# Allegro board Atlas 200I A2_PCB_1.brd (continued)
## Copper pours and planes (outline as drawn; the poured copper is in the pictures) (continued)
V_DV33_HUB on ART04: 93.03,95.62 96.99,95.62 98.65,97.28 98.65,104.14 97.84,104.95 97.84,105.18 97.54,105.49 96.49,105.49 94.64,103.63 94.64,101.85 93.27,100.48 93.27,99.95 93.45,99.77 96.75,99.77 97.26,99.26 97.26,98.32 96.34,97.41 91.29,97.41 90.27,96.39 90.27,94.49 90.6,94.16 91.57,94.16
V_DVDD_1V0_PHY0 on TOP (solid shape): 11.25,68.53 11.25,64.57 9.21,62.52 9.2,62.52 9.12,62.44 9.12,61.72 8.93,61.53 8.93,60.79 8.85,60.72 7.28,60.72 7.28,60.72 7.28,61.38 7.28,61.84 7.49,62.05 7.85,62.05 7.98,62.18 7.98,62.41 8.64,62.41 8.64,62.71 8.28,62.71 8.28,62.41 7.98,62.41 7.98,63.68 8.38,63.68 8.38,64.11 8.13,64.11 8.13,63.68 7.98,63.68 7.98,64.24 7.85,64.36 7.85,64.42 7.84,64.47 7.82,64.53 7.8,64.58 7.76,64.62 7.72,64.66 7.67,64.7 7.62,64.72 7.62,64.9 8.66,64.9 8.66,65.28 8.38,65.28 8.38,64.9 7.62,64.9 7.62,65.51 7.72,65.61 9.22,65.61 9.25,65.63 9.35,65.63 9.38,65.6 9.43,65.58 9.47,65.55 9.52,65.54 9.58,65.53 9.63,65.53 9.68,65.54 9.73,65.55 9.77,65.58 9.82,65.6 9.85,65.63 9.93,65.63 10.21,65.91 10.21,67.21 9.8,67.61 8.79,67.61 8.69,67.72 8.7,67.72 8.7,67.82 9.47,67.82 9.47,68.25 8.94,68.25 8.94,67.82 8.7,67.82 8.7,68.39 9.02,68.71 11.07,68.71
V_DVDD_1V0_PHY0 on BOTTOM (solid shape): outline of 125 points within 9.3,55.5 18.11,68.94
V_DVDD_1V0_PHY1 on TOP (solid shape): 50.36,28.66 50.71,28.66 51,28.38 51,27.7 50.79,27.5 49.94,27.5 49.92,27.51 49.88,27.54 49.83,27.56 49.79,27.57 49.74,27.58 49.71,27.58 49.63,27.66 49.63,27.83 50.68,27.83 50.68,28.11 49.97,28.11 49.97,27.83 49.63,27.83 49.63,28.26 50.1,28.73 50.36,28.73
V_DVDD_1V0_PHY1 on TOP (solid shape): 57.23,42.47 57.23,42.06 56.58,41.42 56.58,40.63 56.55,40.6 54.93,40.6 54.93,41.26 54.93,41.43 55.4,41.89 55.4,41.91 55.98,41.91 55.98,42.21 56.74,42.21 56.74,42.47 56.34,42.47 56.34,42.21 55.98,42.21 55.98,42.34 55.7,42.34 55.7,41.91 55.4,41.91 55.4,41.93 55.4,41.93 55.4,42.45 55.55,42.6 57.1,42.6
V_STBY_1V8 on TOP (solid shape): 128.09,36.55 128.32,36.55 128.57,36.3 128.57,33.93 128.44,33.8 127.04,33.8 126.95,33.89 126.95,34.14 128.32,34.14 128.32,34.48 128.06,34.48 128.06,34.14 126.95,34.14 126.95,34.17 127.34,34.17 127.34,34.48 127.09,34.48 127.09,34.17 126.95,34.17 126.95,34.54 126.99,34.59 127.03,34.59 127.09,34.61 127.14,34.63 127.18,34.65 127.23,34.69 127.26,34.73 127.3,34.77 127.32,34.82 127.34,34.87 127.35,34.92 127.36,34.95 127.37,34.97 127.64,35.23 127.64,36.58 127.69,36.63 128.02,36.63
V_STBY_1V8 on TOP (solid shape): 95.18,39.65 95.2,39.65 95.23,39.64 95.25,39.62 95.27,39.6 95.28,39.57 95.29,39.54 95.27,39.45 95.27,38.09 95.26,38.06 95.24,38.01 95.23,37.95 95.22,37.87 91.99,37.87 91.46,37.34 90.75,37.34 90.73,37.31 90.72,37.3 90.7,37.29 90.7,37.09 90.7,37.08 90.7,36.5 90.18,35.99 89.4,35.99 89.4,36.24 90.09,36.24 90.09,36.5 89.4,36.5 89.4,36.83 89.27,36.96 89,36.96 88.93,37.02 88.93,37.74 91.24,37.74 91.24,38.15 90.98,38.15 90.98,37.74 88.93,37.74 88.93,37.78 89.02,37.87 89.7,37.87 89.7,38.12 89.91,38.33 89.91,39.04 90.52,39.65
V_STBY_1V8 on TOP (solid shape): outline of 90 points within 109.58,47.73 126.77,71.37
V_STBY_1V8 on BOTTOM (solid shape): outline of 14136 points within 0.91,6.22 129.29,119.49
V_STBY_1V8 on ART04 (solid shape): outline of 300 points within 71.27,86.21 101.37,114.5
V_STBY_1V8 on TOP: 80.37,82.6 83.87,82.6 83.92,82.55 83.92,82.17 83.87,82.12 83.72,82.12 83.52,81.92 83.52,81.36 83.26,81.1 81.81,81.1 81.31,80.59 81.31,79.45 80.77,78.92 80.34,78.92 80.04,78.61 80.04,76.89 80.23,76.69 84.02,76.69 84.58,76.12 84.58,75.67 84.48,75.56 79.71,75.56 79.17,75.03 71.55,75.03 70.94,75.64 70.94,76.02 71.09,76.17 71.6,76.17 71.83,76.4 71.83,88.24 72.52,88.93 73.63,88.93 73.79,88.77 73.79,86.16 73.43,85.8 73.43,81.43 73.61,81.25 74.42,81.25 74.75,80.92 74.75,80.29 74.57,80.11 73.61,80.11 73.43,79.93 73.43,76.02 73.84,75.62 77.9,75.62 78.82,76.53 78.82,78.44 79.22,78.84 79.22,82.19 79.62,82.59 ; 5 cut-outs
V_STBY_3V3 on TOP (solid shape): 128.68,40.51 128.68,38.48 128.27,38.08 128.2,38.07 128.14,38.05 127.66,38.05 127.62,38.09 127.62,39.46 127.2,39.88 126.49,39.88 126.39,39.98 126.39,40.71 126.47,40.79 128.39,40.79
V_STBY_3V3 on TOP (solid shape): 3.59,48.18 3.59,47.48 3.33,47.22 1.47,47.22 1.35,47.09 0.86,47.09 0.64,47.32 0.64,47.71 3.3,47.71 3.3,48.05 2.92,48.05 2.92,47.71 0.64,47.71 0.64,48.16 0.84,48.36 3.41,48.36
V_STBY_3V3 on TOP (solid shape): 57.6,44.7 57.64,44.7 57.99,44.35 57.99,43.96 58.15,43.79 58.15,42.48 58.08,42.41 57.49,42.41 57.4,42.49 57.4,42.7 57.99,42.7 57.99,43.18 57.66,43.18 57.66,42.7 57.4,42.7 57.4,43.41 57.25,43.56 57.25,43.61 57.2,43.61 57.07,43.74 56.03,43.74 55.88,43.89 55.88,44.8 56.08,45 57.3,45
V_STBY_3V3 on TOP (solid shape): 84.41,110.92 89.43,110.92 89.56,110.79 89.56,109.96 89.43,109.83 83.45,109.83 83.26,110.02 83.26,110.15 88.23,110.15 88.23,110.57 87.92,110.57 87.92,110.15 83.26,110.15 83.26,110.59 83.9,110.59 83.9,111 83.49,111 83.49,110.59 83.26,110.59 83.26,111.22 83.36,111.32 84.01,111.32
V_STBY_3V3 on TOP (solid shape): 25.17,85.65 25.17,84.38 25.25,84.3 26.06,84.3 26.16,84.2 26.16,83.19 26.14,83.17 26.14,83.07 25.96,82.88 24.05,82.88 23.75,83.19 23.75,83.44 23.32,83.87 22.27,83.87 21.89,83.49 21.4,83.49 21.31,83.57 21.31,83.9 21.8,83.9 21.8,84.84 24.82,84.84 24.82,85.12 24.38,85.12 24.38,84.84 21.8,84.84 21.8,85.46 21.55,85.46 21.55,83.9 21.31,83.9 21.31,85.88 21.41,85.98 24.84,85.98
V_STBY_3V3 on TOP (solid shape): 114.17,27.66 114.17,26.42 114.2,26.39 114.2,26.34 114.25,26.34 114.33,26.26 116.04,26.26 116.12,26.18 116.12,25.21 115.86,24.94 112.9,24.94 112.75,25.1 112.75,25.25 115.87,25.25 115.87,25.53 114.3,25.53 114.3,25.25 112.75,25.25 112.75,25.76 115.87,25.76 115.87,26.04 114.3,26.04 114.3,25.76 112.75,25.76 112.75,26.44 113.23,26.92 113.23,27.38 113.43,27.58 113.67,27.58 113.69,27.61 113.71,27.61 113.71,27.63 113.79,27.71 114.12,27.71
V_STBY_3V3 on TOP (solid shape): 98.86,20.12 98.86,19.68 99.16,19.38 99.16,15.47 98.98,15.29 98.3,15.29 98.04,15.04 98.04,12.98 97.71,12.65 96.82,12.65 96.62,12.85 96.62,13.47 97.39,13.47 97.39,13.46 97.79,13.46 97.79,13.77 96.62,13.77 96.62,16.09 97.39,16.09 97.39,16.08 97.79,16.08 97.79,16.39 96.62,16.39 96.62,17.27 98.7,17.27 98.7,17.63 98.25,17.63 98.25,17.27 96.62,17.27 96.62,18.54 98.7,18.54 98.7,18.87 98.25,18.87 98.25,18.54 96.62,18.54 96.62,18.71 97.39,18.71 97.39,18.72 97.76,18.72 97.76,19 96.62,19 96.62,19.68 97.89,19.68 98.17,19.96 98.17,20.27 98.25,20.35 98.63,20.35
V_STBY_3V3 on TOP (solid shape): 47.47,118.33 47.47,117.91 47.61,117.91 47.61,117.73 47.67,117.73 47.7,117.7 47.7,116.92 47.55,116.76 47.02,116.76 46.99,116.74 46.94,116.74 46.94,116.69 46.14,115.89 45.22,115.89 44.55,115.21 44.55,114.86 44.53,114.84 44.53,113.94 44.55,113.92 44.55,113.36 44.42,113.36 44.42,112.65 43.1,112.65 42.98,112.78 42.98,112.83 44.15,112.83 44.15,113.23 43.66,113.23 43.66,112.83 42.98,112.83 42.98,114.05 44.15,114.05 44.15,114.33 43.66,114.33 43.66,114.05 42.98,114.05 42.98,114.83 42.85,114.96 42.85,117.02 42.9,117.07 47.52,117.07 47.52,117.53 47.22,117.53 47.22,117.07 42.9,117.07 43.1,117.27 46.56,117.27 46.89,117.6 46.89,118.34 46.92,118.37 47.42,118.37
V_STBY_3V3 on TOP (solid shape): 114.83,45.82 114.83,45.34 114.43,44.93 114.43,43.64 114.55,43.51 115.93,43.51 116.07,43.37 116.07,42.55 116.04,42.52 114.43,42.52 114.37,42.45 114.2,42.45 114.2,40.84 114.2,40.84 114.27,40.77 116.61,40.77 116.84,40.54 116.84,39.24 116.62,39.02 112.71,39.02 112.6,39.14 112.6,39.27 115.82,39.27 115.82,39.52 114.35,39.52 114.35,39.27 112.6,39.27 112.6,39.75 115.82,39.75 115.82,40.03 114.35,40.03 114.35,39.75 112.6,39.75 112.6,40.26 115.82,40.26 115.82,40.52 114.35,40.52 114.35,40.26 112.6,40.26 112.6,41.05 113.41,41.05 113.41,41.33 112.95,41.33 112.95,41.05 112.6,41.05 112.6,42.39 113.36,42.39 113.36,42.7 112.9,42.7 112.9,42.39 112.6,42.39 112.6,42.77 115.8,42.77 115.8,43.03 114.37,43.03 114.37,42.77 112.6,42.77 112.6,43.21 112.47,43.34 112.47,45.67 112.78,45.97 114.68,45.97
V_STBY_3V3 on TOP (solid shape): 108.71,101.37 108.71,92.86 108.84,92.74 108.84,92.66 108.92,92.66 109.32,92.25 109.32,91.84 109.25,91.77 106.97,91.77 106.4,92.34 106.4,92.96 108.43,92.96 108.43,93.24 108.05,93.24 108.05,92.96 106.4,92.96 106.4,94.01 108.43,94.01 108.43,94.28 108.05,94.28 108.05,94.01 106.4,94.01 106.4,95.05 108.43,95.05 108.43,95.33 108.05,95.33 108.05,95.05 106.4,95.05 106.4,96.01 108.43,96.01 108.43,96.29 108.05,96.29 108.05,96.01 106.4,96.01 106.4,97.03 108.41,97.03 108.41,97.31 108.03,97.31 108.03,97.03 106.4,97.03 106.4,98.07 108.43,98.07 108.43,98.35 108.05,98.35 108.05,98.07 106.4,98.07 106.4,99.06 108.43,99.06 108.43,99.34 108.05,99.34 108.05,99.06 106.4,99.06 106.4,100.08 108.43,100.08 108.43,100.36 108.05,100.36 108.05,100.08 106.4,100.08 106.4,100.84 106.65,101.09 108.43,101.09 108.43,101.37 108.05,101.37 108.05,101.09 106.65,101.09 107.21,101.65 108.43,101.65
V_STBY_3V3 on TOP (solid shape): outline of 87 points within 124.05,90.86 125.3,100.89
V_STBY_3V3 on TOP (solid shape): outline of 116 points within 0.69,83.67 8.13,89.54
V_STBY_3V3 on TOP (solid shape): outline of 331 points within 68.59,22.45 95.45,40.14
V_STBY_3V3 on BOTTOM (solid shape): outline of 2939 points within 88.77,14.02 121.18,55.92
V_STBY_3V3 on BOTTOM (solid shape): outline of 10801 points within 0.51,46.94 118.85,115.87
V_STBY_3V3 on ART03 (solid shape): outline of 494 points within 113.59,25.6 129.64,41.02
V_STBY_3V3 on ART03 (solid shape): outline of 1104 points within 117.25,53.49 133.6,101.17
V_STBY_3V3 on TOP: 107.19,71.6 107.19,72.64 103.91,72.64 103.45,72.19 103.45,71.65 103.61,71.5 107.09,71.5
V_STBY_3V3 on ART04: 125.48,100.01 106.16,100.01 104.85,98.7 104.85,94.39 105.84,93.4 120.42,93.4 124.56,89.26 124.56,74.55 124.87,74.24 126.21,74.24 127.23,75.26 127.23,90.27 126.44,91.06 126.44,95.63 125.98,96.09 125.98,99.5
V_STBY_3V3 on ART04: 107.64,116.69 110.21,114.12 112.88,114.12 113.21,114.45 113.21,118.62 112.93,118.9 91.08,118.9 86.46,114.27 86.46,113.36 87.38,112.45 87.38,110.29 87.71,109.96 89.2,109.96 91.72,112.47 96.55,112.47 100.76,116.69
V_STBY_3V3 on ART04: 58.01,41.27 58.04,41.27 58.32,41 59.59,41 62.08,38.51 64.21,38.51 64.9,37.82 64.9,36.42 65.35,35.96 65.35,33.58 67.72,31.22 69.44,31.22 69.52,31.29 69.52,33.1 67.59,35.03 67.59,36.93 66.29,38.23 66.29,39.98 65.1,41.17 61.87,41.17 60.17,42.88 60.17,43 58.67,44.5 58.67,44.9 58.38,45.19 57.23,45.19 56.97,44.93 56.97,42.32
V_STBY_3V3_VCXO1 on TOP (solid shape): 83.95,115.98 83.95,114.45 84.43,113.97 84.43,113.33 84.23,113.13 84.23,111.79 84.1,111.66 82.16,111.66 82.02,111.8 82.02,111.91 83.79,111.91 83.79,112.32 83.44,112.32 83.44,111.91 82.02,111.91 82.02,112.88 81.84,113.06 80.47,113.06 80.14,112.72 77.83,112.72 77.61,112.94 77.61,113.02 78.16,113.02 78.16,113.05 80.14,113.05 80.14,113.43 79.84,113.43 79.84,113.05 79.19,113.05 79.19,113.42 78.88,113.42 78.88,113.05 78.16,113.05 78.16,113.42 77.87,113.42 77.87,113.02 77.61,113.02 77.61,113.49 84.05,113.49 84.05,113.82 83.64,113.82 83.64,113.49 77.61,113.49 77.61,113.82 77.04,114.39 76.62,114.39 76.58,114.43 76.58,115.72 76.82,115.96 78.59,115.96 78.77,115.79 78.77,114.48 79.33,113.91 80.54,113.91 80.54,113.88 80.57,113.84 80.6,113.79 80.63,113.76 80.68,113.73 80.72,113.7 80.77,113.68 80.82,113.67 80.87,113.67 80.93,113.67 80.98,113.68 81.03,113.7 81.07,113.73 81.11,113.76 81.15,113.79 81.18,113.84 81.2,113.88 81.21,113.91 82.04,113.91 82.47,114.34 82.47,115.9 82.6,116.03 83.9,116.03
V_STBY_5V0 on TOP (solid shape): 77.8,3.99 77.8,1.91 77.67,1.78 74.55,1.78 74.27,2.06 74.27,3.73 74.65,4.11 77.67,4.11
V_STBY_5V0 on TOP (solid shape): 129.05,63.4 129.05,59.91 128.79,59.66 125.86,59.66 125.61,59.91 125.61,63.4 125.86,63.65 128.79,63.65
V_STBY_5V0 on TOP (solid shape): 46.48,36.35 46.48,34.04 46.28,33.83 46.28,33.12 46.25,33.1 45.62,33.1 44.93,33.78 44.93,36.17 45.26,36.5 46.33,36.5
V_STBY_5V0 on TOP (solid shape): 57.61,21.79 57.61,19.48 57.4,19.28 57.4,18.57 57.38,18.54 56.74,18.54 56.06,19.23 56.06,21.62 56.39,21.95 57.45,21.95
V_STBY_5V0 on TOP (solid shape): 71.65,30.99 71.65,28.14 71.5,27.99 70.59,27.99 69.77,27.18 69.77,26.16 69.6,25.98 68.87,25.98 68.36,25.48 68.36,23.99 67.84,23.47 67.84,21.58 67.2,20.94 67.2,17.13 67.16,17.09 66.15,17.09 65.74,17.09 65.56,17.27 65.56,17.68 65.56,17.69 65.56,24.71 66.37,25.53 66.88,25.53 67.43,26.07 67.43,27.73 69.48,29.78 69.48,30.62 70.03,31.17 71.48,31.17
V_STBY_5V0 on BOTTOM (solid shape): outline of 2418 points within 44.61,3.3 77.5,36.3
V_STBY_5V0 on ART03 (solid shape): outline of 1039 points within 74.21,2.74 133.58,34.96
V_STBY_5V0 on ART04 (solid shape): outline of 1238 points within 100.94,32.65 134.49,112.9
V_STBY_5V0 on TOP: 98.86,94.67 98.86,90.86 99.16,90.55 100.43,90.55 101.37,91.49 101.37,93.07 105.69,97.38 105.69,101.47 105.16,102.01 101.07,102.01 100.86,101.8 100.86,95.5 100.28,94.92 99.11,94.92
V_STBY_5V0_HDMI0 on TOP (solid shape): 67.06,30.94 67.06,28.14 66.8,27.89 65.68,27.89 65.2,27.41 64.34,27.41 64.21,27.53 64.21,28.74 64.5,29.03 64.57,29.03 64.72,29.18 64.8,29.18 64.8,29.26 65.01,29.47 65.1,29.46 65.35,29.57 65.46,29.82 65.44,29.94 65.38,30.04 65.35,30.07 65.41,30.12 65.41,30.91 65.58,31.09 66.9,31.09
V_STBY_5V0_HDMI1 on TOP (solid shape): 75.59,9.63 75.59,8.48 76.02,8.05 77.65,8.05 77.77,7.92 77.77,5.77 77.65,5.64 74.22,5.64 74.09,5.77 74.09,10.21 74.32,10.44 74.78,10.44
V_STBY_12V0 on TOP (solid shape): 105.89,36.68 105.89,35.43 105.05,34.59 105.05,33.07 105.18,32.94 105.18,32.93 105.25,32.86 105.25,32.62 105.48,32.62 105.55,32.56 105.56,32.56 105.74,32.38 108.62,32.38 108.75,32.26 108.75,31.95 109.78,31.95 109.78,30.18 108.97,29.36 105.28,29.36 105.08,29.57 105.08,30.58 105.03,30.63 105.03,30.83 104.83,30.83 104.75,30.91 101.93,30.91 101.73,31.11 101.73,31.37 109.56,31.37 109.56,31.73 109.3,31.73 109.3,31.37 101.73,31.37 101.73,33.93 103.35,35.56 103.35,36.6 103.68,36.93 105.64,36.93
V_STBY_12V0 on TOP (solid shape): outline of 122 points within 71.63,19.15 81.66,26.36
V_STBY_12V0 on TOP (solid shape): outline of 340 points within 27.25,43.94 42.62,57.67
V_STBY_12V0 on BOTTOM (solid shape): outline of 2036 points within 126.97,26.47 133.93,111.06
V_STBY_12V0 on BOTTOM (solid shape): outline of 12269 points within 20.62,22.82 106.71,62.51
V_STBY_12V0 on ART03 (solid shape): outline of 201 points within 112.75,108.05 129.26,113.31
V_STBY_12V0 on ART04 (solid shape): outline of 233 points within 112.75,108.05 129.26,113.31
V_STBY_12V0 on ART04: 109.75,22.68 114.9,17.53 129.42,17.53 133.88,21.99 133.88,29.82 133.45,30.25 130.58,30.25 130.12,29.79 130.12,25.37 128.5,23.74 124.04,23.74 122.53,25.25 114.33,25.25 105.41,34.16 103.15,34.16 102.67,33.68 102.67,25.65 105.64,22.68
V_VCC_1V8_EMMC on TOP (solid shape): 60.45,93.73 60.45,92.71 60.33,92.58 60.25,92.66 60.25,92.74 60.17,92.74 60.15,92.76 58.45,92.76 58.42,92.74 58.37,92.74 58.37,92.68 58.09,92.41 55.96,92.41 55.68,92.68 55.68,93.12 59.97,93.12 59.97,93.55 59.66,93.55 59.66,93.12 55.68,93.12 55.68,93.14 58.93,93.14 58.93,93.55 58.67,93.55 58.67,93.14 55.68,93.14 55.68,93.83 55.7,93.85 60.33,93.85
V_VCC_1V8_EMMC on BOTTOM (solid shape): outline of 127 points within 33.22,79.03 46.89,89.87
V_VCC_1V8_EMMC on ART03 (solid shape): outline of 1708 points within 3.78,85.42 58.17,100.17
V_VCC_3V3_BUF on TOP (solid shape): 49.04,113.41 49.04,113.09 49.1,113.03 49.1,112.71 49.04,112.65 49.04,112.16 49.1,112.11 49.1,111.12 48.77,110.79 44.86,110.79 44.68,110.97 44.68,112.7 44.74,112.7 44.74,112.85 45.39,112.85 45.39,113.21 44.98,113.21 44.98,112.85 44.74,112.85 44.74,113.29 44.86,113.41 49.04,113.41
V_VCC_3V3_BUF on ART03 (solid shape): outline of 883 points within 46.48,110.87 72.14,118.87
V_VCC_3V3_EMMC on TOP (solid shape): 38.43,117.45 38.43,116.46 37.97,116 34.16,116 33.81,115.65 33.81,115.29 33.73,115.21 32.97,115.21 32.26,115.21 32.16,115.32 32.16,115.6 33.53,115.6 33.53,116 33.25,116 33.25,115.6 32.16,115.6 32.16,116.26 33.53,116.26 33.53,116.69 33.25,116.69 33.25,116.26 32.16,116.26 32.16,117.07 32.28,117.2 32.61,117.2 32.87,116.94 36.63,116.94 37.41,117.73 38.15,117.73
V_VCC_3V3_EMMC on ART04 (solid shape): outline of 797 points within 4.72,94.61 33.32,117.45
V_VCCO_3V3_BUF on TOP (solid shape): 62.09,119.45 62.09,118.49 61.84,118.49 61.84,119.24 61.82,119.26 60.61,119.26 60.59,119.24 60.59,118.49 60.34,118.49 60.34,119.23 60.31,119.26 58.18,119.26 58.18,118.49 57,118.49 56.94,118.55 56.9,118.57 56.86,118.6 56.81,118.61 56.77,118.62 56.74,118.62 55.02,118.62 54.99,118.62 54.95,118.61 54.9,118.6 54.86,118.57 54.82,118.55 54.8,118.53 53.67,117.4 52.63,117.4 52.55,117.4 52.55,117.35 52.2,117.35 51.94,117.6 47.98,117.6 47.78,117.81 47.78,117.91 47.78,117.91 47.78,118.08 48.49,118.08 48.49,118.41 48.06,118.41 48.06,118.08 47.78,118.08 47.78,118.57 47.78,118.57 47.78,118.75 47.9,118.87 54,118.87 54.62,119.49 62.05,119.49
V_VCCO_3V3_BUF on ART03 (solid shape): outline of 215 points within 52.07,109.43 62.87,117.98
V_VDD_3V3_PHY0 on TOP (solid shape): 10.06,61.04 10.06,60.35 10.31,60.1 10.79,60.1 10.92,59.97 10.92,58.78 11.1,58.6 11.48,58.6 11.6,58.48 11.59,58.45 11.58,58.4 11.58,58.34 11.59,58.29 11.61,58.23 11.63,58.18 11.67,58.14 11.7,58.1 11.75,58.07 11.8,58.04 11.85,58.02 11.91,58.01 11.94,58.01 11.94,57.73 12.05,57.62 12.05,57.46 11.99,57.4 11.4,57.4 9.42,59.39 10.77,59.39 10.77,59.82 10.49,59.82 10.49,59.39 9.42,59.39 9.32,59.49 9.32,60.33 9.8,60.33 9.8,60.81 9.5,60.81 9.5,60.33 9.32,60.33 9.32,60.99 9.45,61.11 9.98,61.11
V_VDD_3V3_PHY0 on TOP (solid shape): 5.61,50.13 5.64,50.09 5.67,50.05 5.71,50.02 5.74,50.01 5.74,49.43 6.11,49.05 6.11,49 6.17,49 6.29,48.87 6.67,48.87 6.78,48.77 6.78,48.23 6.62,48.08 6.6,48.08 6.35,47.83 6.15,47.83 6.15,47.62 6.1,47.57 6.1,47.27 5.92,47.09 5.74,47.09 5.69,47.1 5.61,47.12 5.53,47.12 5.45,47.1 5.4,47.09 4.82,47.09 4.77,47.1 4.69,47.12 4.6,47.12 4.52,47.1 4.47,47.09 4.24,47.09 4.09,47.24 5.69,47.24 5.69,47.55 5.33,47.55 5.33,47.24 4.09,47.24 4,47.33 4,47.73 4.72,47.73 4.72,48.08 4.24,48.08 4.24,47.73 4,47.73 4,48.29 6.45,48.29 6.45,48.67 6.1,48.67 6.1,48.29 4,48.29 4,48.45 4.13,48.58 4.13,48.58 4.39,48.84 4.39,50.11 4.39,50.11 5.33,50.11 5.36,50.11 5.41,50.12 5.46,50.14 5.5,50.16 5.59,50.16
V_VDD_3V3_PHY0 on BOTTOM (solid shape): outline of 1342 points within 5.36,46.81 23.19,62.38
V_VDD_3V3_PHY1 on TOP (solid shape): 49.1,29.49 50.98,29.49 51.05,29.41 51.05,28.88 51.03,28.85 50.44,28.85 50.42,28.87 50.37,28.89 50.33,28.9 50.28,28.91 50.23,28.91 50.18,28.9 50.13,28.89 50.09,28.87 50.07,28.85 49.91,28.85 49.81,28.75 48.79,28.75 48.67,28.88 48.67,29.01 50.77,29.01 50.77,29.36 50.37,29.36 50.37,29.01 48.67,29.01 48.67,29.42 48.68,29.44 48.71,29.48 48.74,29.52 48.76,29.57 48.76,29.61 48.79,29.64 48.94,29.64
V_VDD_3V3_PHY1 on TOP (solid shape): 58.19,42.01 58.19,41.71 58.01,41.53 58.01,38.61 58.21,38.41 58.21,36.75 58.19,36.73 58.04,36.73 58.01,36.75 58.01,37.43 58.01,37.43 57.82,37.43 57.81,37.43 57.81,36.75 57.78,36.73 57.63,36.73 57.61,36.75 57.61,37.42 57.61,37.43 57.61,38.15 57.23,38.53 57.23,38.68 57.89,38.68 57.89,39.09 57.56,39.09 57.56,38.68 57.23,38.68 57.23,39.6 57.23,39.65 57.89,39.65 57.89,40.06 57.58,40.06 57.58,39.65 57.23,39.65 57.1,39.78 57.1,40.11 57.19,40.2 57.22,40.21 57.26,40.25 57.3,40.29 57.33,40.33 57.35,40.38 57.37,40.43 57.38,40.49 57.38,40.54 57.61,40.54 57.89,40.54 57.89,40.94 57.61,40.94 57.61,40.54 57.38,40.54 57.37,40.59 57.36,40.63 57.34,40.68 57.31,40.72 57.28,40.76 57.26,40.78 57.26,41.01 57.28,41.03 57.31,41.07 57.34,41.11 57.36,41.15 57.37,41.2 57.38,41.25 57.38,41.3 57.37,41.35 57.36,41.4 57.33,41.45 57.84,41.45 57.84,41.81 57.58,41.81 57.58,41.45 57.33,41.45 57.31,41.48 57.28,41.52 57.26,41.54 57.26,41.82 57.53,42.09 58.12,42.09
$7N42483 on TOP (solid shape): 9.08,59.75 9.08,59.5 11.25,57.33 11.25,56.16 11.23,56.13 11.07,56.13 11.05,56.15 11.05,56.84 11.01,56.89 11.01,56.93 10.96,56.93 10.77,57.12 10.66,57.12 10.66,57.13 10.01,57.79 9.68,57.79 9.15,58.32 7.49,58.32 7.28,58.53 7.28,59.83 9,59.83
$8N37109 on TOP (solid shape): 57.1,39.55 57.1,38.35 57.4,38.05 57.4,36.78 57.38,36.75 57.25,36.75 57.23,36.78 57.23,37.34 57.17,37.4 57.17,37.5 56.83,37.5 56.82,37.52 56.82,37.87 56.8,37.99 56.73,38.09 56.08,38.74 55.98,38.81 55.86,38.83 55.13,38.83 54.92,39.03 54.93,39.06 54.93,39.71 56.93,39.71
$8N37208 on BOTTOM: 65.71,42.01 65.91,41.81 65.91,41.22 65.38,40.69 61.85,40.69 59.86,38.7 59.09,38.7 58.57,39.22 58.57,40.79 59.79,42.01
$8N37208 on ART04: 61.52,42.16 61.52,41.66 61.98,41.2 65.61,41.2 66.85,39.95 66.85,37.8 67.11,37.54 67.69,37.54 67.92,37.77 67.92,41.15 66.45,42.62 61.98,42.62
$18N13054 on TOP (solid shape): 116.64,118.26 116.73,118.19 116.7,118.08 116.34,117.66 116.21,117.13 116.55,116.3 117.38,115.96 117.85,116.06 118.23,116.33 119.03,116.33 119.41,116.06 119.88,115.96 120.35,116.06 120.73,116.33 121.08,116.33 121.44,115.98 121.44,108 121.41,107.98 120.85,107.98 120.81,107.98 119.94,107.98 118.67,107.98 118.55,108.1 118.55,112.72 117.73,113.54 114.63,113.54 113.31,114.86 113.31,117.91 113.67,118.26
$19N38557 on TOP (solid shape): 11.02,42.19 11.02,39.34 11.23,39.14 11.23,38.38 11.16,38.31 10.54,38.31 10.54,38.3 8.46,38.3 8.46,38.31 7.87,38.31 7.62,38.56 7.62,39.04 7.95,39.37 8.03,39.37 8.03,39.45 8.08,39.5 8.08,39.67 10.74,39.67 10.74,39.98 10.26,39.98 10.26,39.67 8.86,39.67 8.86,39.98 8.51,39.98 8.51,39.67 8.08,39.67 8.08,40.79 10.69,40.79 10.69,41.1 10.34,41.1 10.34,40.79 8.84,40.79 8.84,41.1 8.48,41.1 8.48,40.79 8.08,40.79 8.08,41.61 10.74,41.61 10.74,42.04 10.49,42.04 10.49,41.61 9.78,41.61 9.78,42.01 9.53,42.01 9.53,41.61 8.81,41.61 8.81,42.01 8.56,42.01 8.56,41.61 8.08,41.61 8.08,42.01 8.41,42.34 10.87,42.34
$19N38557 on ART03 (solid shape): outline of 169 points within 4.38,34.01 15.29,38.81
$19N42379 on TOP (solid shape): 30.71,45.69 30.71,39.01 30.4,38.71 30.4,36.28 30.31,36.18 30.31,36.07 30.16,35.92 29.7,35.92 29.67,35.95 29.67,39.09 29.62,39.14 29.62,39.55 30.38,39.55 30.38,39.85 30.02,39.85 30.02,39.55 29.62,39.55 29.62,40.46 30.38,40.46 30.38,40.77 30.02,40.77 30.02,40.46 29.62,40.46 29.62,41.43 30.38,41.43 30.38,41.73 30.02,41.73 30.02,41.43 29.62,41.43 29.62,42.34 30.38,42.34 30.38,42.65 30.02,42.65 30.02,42.34 29.62,42.34 29.62,43.23 30.38,43.23 30.38,43.54 30.02,43.54 30.02,43.23 29.62,43.23 29.62,44.2 30.38,44.2 30.38,44.5 30.02,44.5 30.02,44.2 29.62,44.2 29.62,45.06 30.4,45.06 30.4,45.47 30,45.47 30,45.06 29.62,45.06 29.62,45.57 29.79,45.75 30.66,45.75
$19N42379 on ART03 (solid shape): 31.27,39.6 31.27,37.39 30.25,36.37 20.42,36.37 20.29,36.5 20.29,39.47 21.51,40.69 30.18,40.69
$19N66318 on TOP (solid shape): 8.28,28.98 8.28,25.25 7.72,24.69 5.66,24.69 5.11,24.13 2.95,24.13 2.67,24.41 2.67,25.1 3.02,25.45 4.11,25.45 4.67,26.01 4.67,28.93 4.75,29 5.28,29 5.28,25.98 5.66,25.6 7.47,25.6 7.7,25.83 7.7,28.95 7.77,29.03 8.23,29.03
$19N66421 on TOP (solid shape): 9.3,23.04 9.3,21.89 9.07,21.67 6.65,21.67 6.3,22.02 6.3,22.83 6.58,23.11 9.22,23.11
$19N66917 on TOP (solid shape): 4.42,22.73 4.42,20.32 4.28,20.18 2.72,20.18 2.55,20.35 2.55,22.97 2.84,23.27 3.89,23.27
$19N67094 on TOP (solid shape): 9.09,20.68 9.09,18.84 9.07,18.64 9.06,18.44 9.06,18.28 8.8,18.02 6.16,18.02 6.05,18.14 6.05,20.78 6.25,20.98 8.79,20.98
$20N78417 on TOP (solid shape): 117.75,18.69 117.75,17.88 117.63,17.75 115.7,17.75 115.57,17.88 115.57,18.69 115.7,18.82 117.63,18.82
$20N78418 on TOP (solid shape): 125.68,17.39 125.68,14.62 125.36,14.3 120.29,14.3 119.91,14.68 119.91,16.81 120.63,17.53 125.53,17.53
$20N78419 on TOP (solid shape): 118.01,22.23 118.01,19.46 117.88,19.33 115.82,19.33 115.7,19.46 115.7,22.23 115.82,22.35 117.88,22.35
$20N115775 on TOP: 14.68,76.23 14.68,72.44 15.32,71.81 20.83,71.81 21.49,72.47 21.49,73.3 21.36,73.43 18.54,73.43 17.58,74.4 17.58,76.3 17.25,76.63 15.09,76.63 ; 1 cut-out
$20N115843 on TOP: 20.95,75.03 22.25,75.03 22.58,74.7 22.58,73.08 22.52,73.02 21.8,73.02 21.79,73.03 21.79,73.46 21.54,73.71 20.95,73.71 20.83,73.84 20.83,74.9
$21N31415 on TOP (solid shape): 87.99,25.91 87.99,22.66 87.76,22.43 85.72,22.43 85.5,22.66 85.5,23.72 85.5,23.85 85.01,24.33 84.38,24.33 84.35,24.36 84.35,24.58 84.94,24.58 84.94,24.84 84.35,24.84 84.35,24.99 84.43,25.07 85.27,25.07 85.37,25.17 85.37,25.96 85.52,26.11 87.78,26.11
$21N31432 on TOP (solid shape): 71.5,20.22 71.5,19.48 72.11,18.87 72.77,18.87 72.77,18.87 72.77,18.63 72.76,18.62 72.26,18.62 72,18.36 71.09,18.36 70.89,18.16 70.89,17.32 70.69,17.12 69.3,17.12 69.3,18.57 71.46,18.57 71.46,18.81 71.09,18.81 71.09,18.57 69.3,18.57 69.3,20.9 70.35,20.9 70.82,20.9

Small or netless copper shapes (teardrops, artwork), in the pictures only: 1 on TOP, 6 on BOTTOM, 2 on ART02, 2 on ART05

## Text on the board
Ref Des/Silkscreen Bottom: GPIO16 | GND | PWM0 | EEPROM_SCL | SPI0_CE1 | SPI0_CE0 | GPIO25 | GPIO24 | GPIO23 | UART0_TX | 5V | PCM_DOUT | PCM_DIN | PCM_CLK | UART0_RX | GPIO26 | PWM1 | GPIO6 | GPIO5 | EEPROM_SDA | SPI0_SCLK | SPI0_MISO | SPI0_MOSI | 3V3 | GPIO22 | GPIO27 | GPIO17 | GPCLK0 | I2C1_SCL | I2C1_SDA | PCM_FS
User.Comments: CR_UNNAMED_3
Ref Des/Silkscreen Top: OFF | ON
DIMENSION: A2 | A3 | A7 | A8 | A4 | A6 | A1 | A5 | 12 | 10 | 11 | 5 | B2 | B1 | 13 | TOP
BODY_CENTER: 10
User.15: FIGURE | SIZE | 8.0 | 10.0 | 16.0 | 26.0 | 28.0 | 30.0 | 36.0 | 44.0 | 138.0 | 168.0 | 189.0 | 20.0 | 43.0 | 45.0 | 53.0 | 63.0 | 125.0 | 128.0 | 177.0 | 64.0x24.0 | 67.0x32.0 | 68.0x28.0 | 71.0x24.0 | 95.0x24.0 | 95.0x28.0 | 98.0x32.0 | 110.0x26.0 | 126.0x32.0 | DRILL CHART: TOP to BOTTOM | ALL UNITS ARE IN MILS | PLATED | NON-PLATED | QTY | 2475 | 4 | 10 | 2 | 18 | 16 | 8 | 3 | 1
